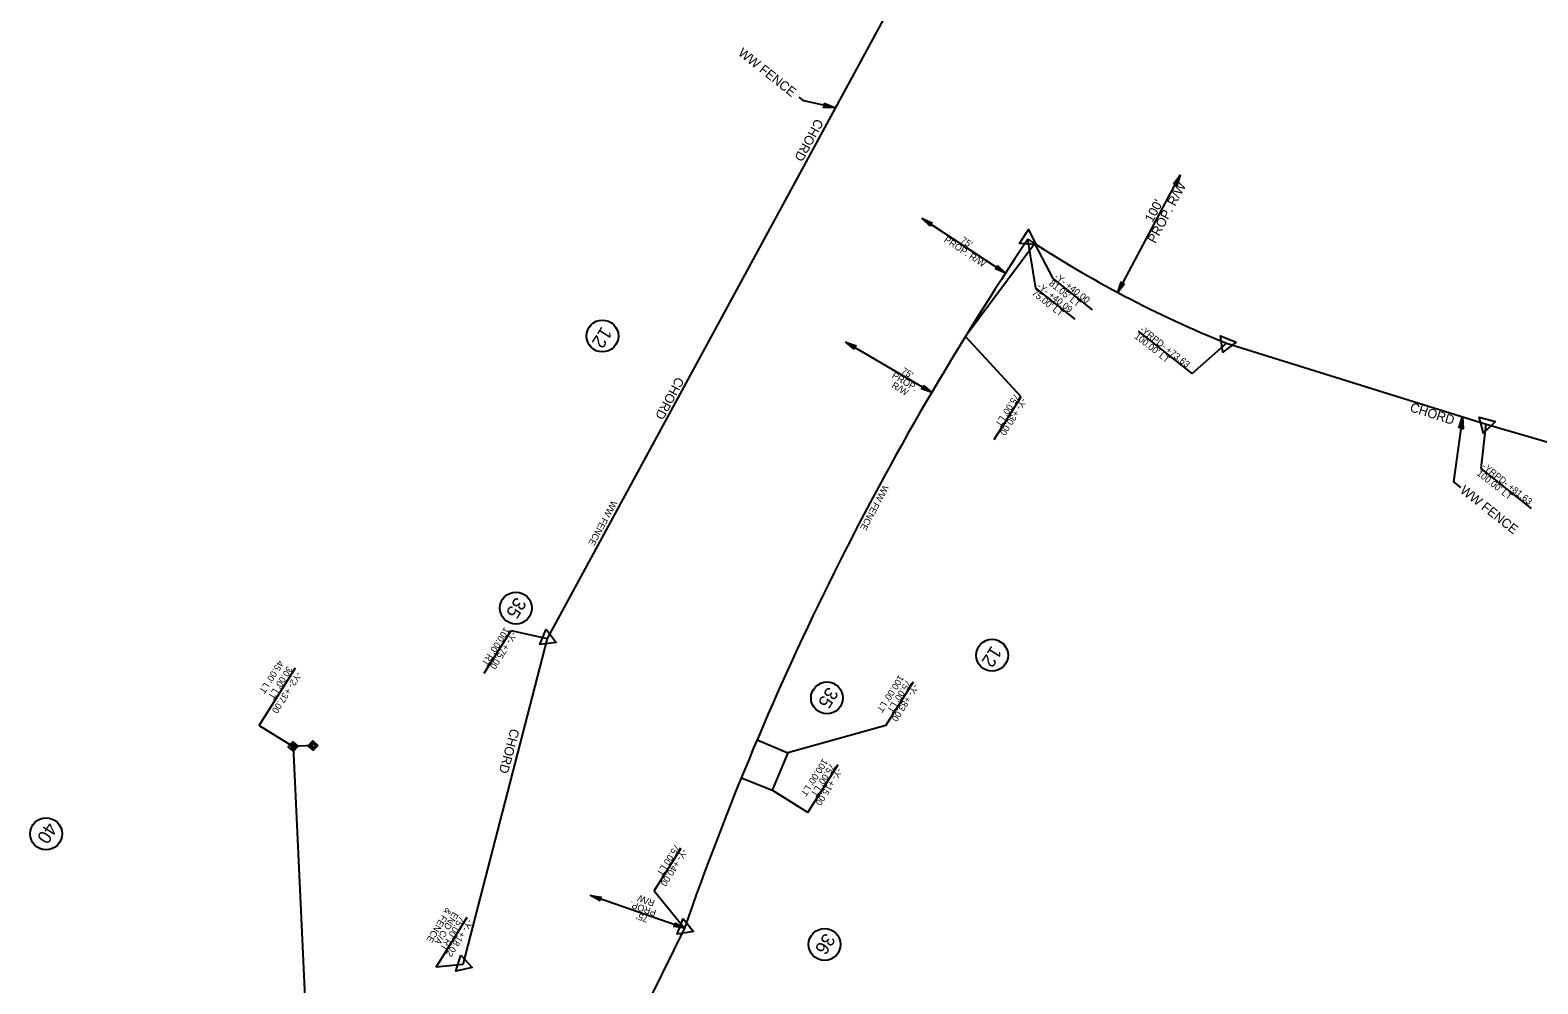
# Model space of a CAD drawing. Extents: x 1779796 to 1783527, y 810952 to 815815.
# Drawn here: x 1780686 to 1781820, y 812223 to 812940 of the extents above; entities that cross this region are included whole.
import ezdxf

# ---------------------------------------------------------------- set-up
doc = ezdxf.new("R2010")
doc.units = 0
for name, color, linetype in [('Prop Dimension', 7, 'Continuous'), ('Prop Dimension Text', 7, 'Continuous'), ('Prop Easement Construction', 7, 'Continuous'), ('Prop Easement Construction Station Offsets', 7, 'Continuous'), ('Prop Easement Permanent Utility', 7, 'Continuous'), ('Prop Easement Permanent Utility Station Offsets', 7, 'Continuous'), ('Prop Easement Temporary Drainage', 7, 'Continuous'), ('Prop Easement Temporary Drainage Station Offsets', 7, 'Continuous'), ('Prop Fence Woven Wire', 7, 'Continuous'), ('Prop Parcel Number CELL', 7, 'Continuous'), ('Prop Parcel Number Text', 7, 'Continuous'), ('Prop ROW Marker CELL', 7, 'Continuous'), ('Prop ROW Permanent Easement CELL', 7, 'Continuous'), ('Prop ROW RW CA Lines', 7, 'Continuous'), ('Prop ROW Station Offsets', 7, 'Continuous'), ('Prop Terminator CELL', 7, 'Continuous')]:
    doc.layers.add(name, color=color, linetype=linetype)

msp = doc.modelspace()

# ---------------------------------------------------------------- linework, layer by layer
at = {"layer": 'Prop Dimension'}
for p, q in [((1781267.9, 812886.9), (1781264.4, 812889.7)), ((1781291.6, 812881.6), (1781267.9, 812886.9)), ((1781504.1, 812742.7), (1781551.1, 812831)), ((1781356.9, 812798.3), (1781419.7, 812757.4)), ((1781299.4, 812705.5), (1781364.1, 812667.6)), ((1781763.4, 812649.3), (1781756.6, 812600.3)), ((1781756.6, 812600.3), (1781762, 812596.1)), ((1781178.2, 812264.6), (1781107.4, 812289.2))]:
    msp.add_line(p, q, dxfattribs=at)
at = {"layer": 'Prop Easement Construction'}
msp.add_line((1781441.6, 812779.5), (1781389.4, 812709.6), dxfattribs=at)
at = {"layer": 'Prop Easement Construction Station Offsets'}
for p, q in [((1781485.1, 812729.8), (1781455.5, 812753.3)), ((1781411.1, 812632.3), (1781431.3, 812664.2))]:
    msp.add_line(p, q, dxfattribs=at)
for points in [[(1781455.5, 812753.3), (1781441.6, 812779.5)], [(1781431.3, 812664.2), (1781389.4, 812709.6)]]:
    msp.add_lwpolyline(points, dxfattribs=at)
at = {"layer": 'Prop Easement Permanent Utility'}
for p, q in [((1780898.7, 812402), (1780883.7, 812401.3)), ((1780883.7, 812401.3), (1780902.3, 812002.2))]:
    msp.add_line(p, q, dxfattribs=at)
at = {"layer": 'Prop Easement Permanent Utility Station Offsets'}
for q in [(1780885.6, 812460.4), (1780883.7, 812401.3)]:
    msp.add_line((1780858.1, 812417), q, dxfattribs=at)
at = {"layer": 'Prop Easement Temporary Drainage'}
for p, q in [((1781232.8, 812406.4), (1781255.8, 812396.6)), ((1781255.8, 812396.6), (1781244, 812368.4)), ((1781220.9, 812377.8), (1781244, 812368.4))]:
    msp.add_line(p, q, dxfattribs=at)
at = {"layer": 'Prop Easement Temporary Drainage Station Offsets'}
for p, q in [((1781329.6, 812417.1), (1781350.4, 812449.9)), ((1781270.9, 812351.7), (1781293.7, 812387.7))]:
    msp.add_line(p, q, dxfattribs=at)
for points in [[(1781329.6, 812417.1), (1781255.8, 812396.6)], [(1781270.9, 812351.7), (1781244, 812368.4)]]:
    msp.add_lwpolyline(points, dxfattribs=at)
at = {"layer": 'Prop Fence Woven Wire'}
for p, q in [((1781332.6, 812957.1), (1781074.9, 812482.4)), ((1781585.9, 812704.6), (1781781.1, 812643.8)), ((1781781.1, 812643.8), (1781913.7, 812605.1)), ((1781074.9, 812482.4), (1781011.4, 812237.2)), ((1781178.2, 812264.6), (1781097.3, 812100.9))]:
    msp.add_line(p, q, dxfattribs=at)
for centre, radius, start, end in [((1783308.8, 811526), 2255, 146.1271, 160.8792), ((1781908.4, 813501.8), 860, 236.7199, 247.9703)]:
    msp.add_arc(centre, radius, start, end, dxfattribs=at)
at = {"layer": 'Prop Parcel Number CELL'}
for p, q in [((1781116.4, 812710), (1781116.4, 812710)), ((1781051.3, 812505.4), (1781051.3, 812505.4)), ((1781409.5, 812469.9), (1781409.5, 812469.9)), ((1781285.3, 812437.8), (1781285.3, 812437.8)), ((1780697.9, 812335.6), (1780697.9, 812335.6)), ((1781283.5, 812252.4), (1781283.5, 812252.4))]:
    msp.add_line(p, q, dxfattribs=at)
for centre in [(1781116.4, 812710), (1781051.3, 812505.4), (1781409.5, 812469.9), (1781285.3, 812437.8), (1780697.9, 812335.6), (1781283.5, 812252.4)]:
    msp.add_circle(centre, 12, dxfattribs=at)
at = {"layer": 'Prop ROW Marker CELL'}
for p, q in [((1781436.5, 812782.8), (1781436.5, 812782.8)), ((1781585.9, 812704.6), (1781585.9, 812704.6)), ((1781781.1, 812643.8), (1781781.1, 812643.8)), ((1781074.9, 812482.4), (1781074.9, 812482.4)), ((1780883.7, 812401.3), (1780883.7, 812401.3)), ((1780898.7, 812402), (1780898.7, 812402)), ((1781178.2, 812264.6), (1781178.2, 812264.6)), ((1781011.4, 812237.2), (1781011.4, 812237.2))]:
    msp.add_line(p, q, dxfattribs=at)
for points in [[(1781442.5, 812778.8), (1781430.1, 812779.6), (1781437, 812790)], [(1781593, 812705.5), (1781583.2, 812697.9), (1781581.4, 812710.2)], [(1781788.1, 812645.7), (1781779.3, 812636.9), (1781776, 812648.9)], [(1781074.1, 812489.6), (1781081.6, 812479.6), (1781069.2, 812478.1)], [(1781177.2, 812271.8), (1781184.9, 812262), (1781172.6, 812260.1)], [(1781009.8, 812244.3), (1781018.3, 812235.1), (1781006.1, 812232.3)]]:
    msp.add_lwpolyline(points, close=True, dxfattribs=at)
at = {"layer": 'Prop ROW Permanent Easement CELL'}
for points in [[(1780887.3, 812401.4), (1780883.9, 812397.7), (1780880.1, 812401.1), (1780883.5, 812404.9)], [(1780885.5, 812401.4), (1780883.8, 812399.5), (1780881.9, 812401.2), (1780883.6, 812403.1)], [(1780902.3, 812402.1), (1780898.8, 812398.4), (1780895.1, 812401.8), (1780898.5, 812405.6)], [(1780900.5, 812402.1), (1780898.8, 812400.2), (1780896.9, 812401.9), (1780898.6, 812403.8)]]:
    msp.add_lwpolyline(points, close=True, dxfattribs=at)
at = {"layer": 'Prop ROW RW CA Lines'}
for p, q in [((1781781.1, 812643.8), (1781913.7, 812605.1)), ((1781074.9, 812482.4), (1781011.4, 812237.2)), ((1781178.2, 812264.6), (1781097.3, 812100.9))]:
    msp.add_line(p, q, dxfattribs=at)
for points in [[(1781332.6, 812957.1), (1781074.9, 812482.4)], [(1781585.9, 812704.6), (1781781.1, 812643.8)]]:
    msp.add_lwpolyline(points, dxfattribs=at)
for centre, radius, start, end in [((1783308.8, 811526), 2255, 146.1271, 160.8792), ((1781908.4, 813501.8), 860, 236.7199, 247.9703)]:
    msp.add_arc(centre, radius, start, end, dxfattribs=at)
at = {"layer": 'Prop ROW Station Offsets'}
for p, q in [((1781472, 812722.6), (1781442.5, 812746)), ((1781559.9, 812681.7), (1781519.7, 812713.6)), ((1781815.2, 812580.4), (1781777.3, 812610.4)), ((1781027.4, 812456.5), (1781047.7, 812488.4)), ((1781155.3, 812292.8), (1781175.6, 812324.8)), ((1781155.3, 812292.8), (1781178.2, 812264.6)), ((1780991.3, 812235.4), (1781014.7, 812273)), ((1781011.4, 812237.2), (1780991.3, 812235.4))]:
    msp.add_line(p, q, dxfattribs=at)
for points in [[(1781442.5, 812746), (1781436.5, 812782.8)], [(1781559.9, 812681.7), (1781585.9, 812704.6)], [(1781777.3, 812610.4), (1781781.1, 812643.8)], [(1781047.7, 812488.4), (1781074.9, 812482.4)]]:
    msp.add_lwpolyline(points, dxfattribs=at)
at = {"layer": 'Prop Terminator CELL'}
for points in [[(1781283.1, 812885.1), (1781291.6, 812881.6), (1781282.4, 812882), (1781283.9, 812883.3)], [(1781546.1, 812824.5), (1781551.1, 812831), (1781548.6, 812823.1), (1781547.8, 812824.7)], [(1781362.9, 812792.7), (1781356.9, 812798.3), (1781364.5, 812795.1), (1781362.8, 812794.4)], [(1781413.7, 812763), (1781419.7, 812757.4), (1781412.1, 812760.6), (1781413.7, 812761.2)], [(1781509.1, 812749.2), (1781504.1, 812742.7), (1781506.7, 812750.6), (1781507.4, 812749)], [(1781305.7, 812700.2), (1781299.4, 812705.5), (1781307.2, 812702.6), (1781305.6, 812701.9)], [(1781357.8, 812672.9), (1781364.1, 812667.6), (1781356.4, 812670.4), (1781358, 812671.2)], [(1781760.7, 812640.6), (1781763.4, 812649.3), (1781763.8, 812640.1), (1781762.4, 812641.5)], [(1781114.6, 812285.2), (1781107.4, 812289.2), (1781115.5, 812287.9), (1781114.1, 812286.9)], [(1781171, 812268.6), (1781178.2, 812264.6), (1781170, 812265.9), (1781171.5, 812267)]]:
    msp.add_lwpolyline(points, close=True, dxfattribs=at)

# ---------------------------------------------------------------- texts
at = {"layer": 'Prop Dimension Text'}
for s, height, rotation, p in [('WW FENCE', 7, 321.6309, (1781217.9, 812921.8)), ('CHORD', 7, 241.5491, (1781276.9, 812874)), ('PROP. R/W', 7, 61.9551, (1781532.2, 812779.2)), ("100'", 7, 61.9551, (1781530.2, 812794.9)), ('PROP. R/W', 5, 326.335, (1781372.9, 812781.3)), ("75'", 5, 326.335, (1781385.4, 812780.9)), ("75'", 5, 329.0187, (1781340.7, 812682.4)), ('CHORD', 7, 241.5491, (1781172.1, 812679.8)), ('R/W', 5, 329.0187, (1781333.5, 812671.5)), ('PROP.', 5, 329.0187, (1781333.7, 812679)), ('CHORD', 7, 342.367, (1781723.3, 812653.5)), ('WW FENCE', 5, 242.0444, (1781327.5, 812598.3)), ('WW FENCE', 7, 321.6309, (1781761, 812592.8)), ('WW FENCE', 5, 241.541, (1781123.3, 812586.7)), ('CHORD', 7, 255.0712, (1781047.3, 812415.2)), ('R/W', 5, 160.1616, (1781156.2, 812285.5)), ('PROP.', 5, 160.1616, (1781157.4, 812278.1)), ("75'", 5, 160.1616, (1781151.3, 812273.4))]:
    msp.add_text(s, height=height, rotation=rotation, dxfattribs=at).set_placement(p)
at = {"layer": 'Prop Easement Construction Station Offsets'}
for s, rotation, p in [('-Y- +40.00', 321.6309, (1781456, 812753.8)), ("81.05' LT", 321.6309, (1781451.9, 812748.7)), ("75.00' LT", 237.6015, (1781426.4, 812667.2)), ('-Y- +30.00', 237.6015, (1781431.9, 812663.8))]:
    msp.add_text(s, height=5, rotation=rotation, dxfattribs=at).set_placement(p)
at = {"layer": 'Prop Easement Permanent Utility Station Offsets'}
for s, p in [("45.00' LT", (1780872.8, 812466.5)), ("30.00' LT", (1780879.5, 812462.2)), ('-Y2- +37.00', (1780886.3, 812457.9))]:
    msp.add_text(s, height=5, rotation=237.5792, dxfattribs=at).set_placement(p)
at = {"layer": 'Prop Easement Temporary Drainage Station Offsets'}
for s, p in [("100.00' LT", (1781339.5, 812455.5)), ("75.00' LT", (1781345, 812452)), ('-Y- +83.00', (1781350.5, 812448.6)), ("100.00' LT", (1781282.2, 812392.5)), ("75.00' LT", (1781287.7, 812389)), ('-Y- +15.00', (1781293.2, 812385.5))]:
    msp.add_text(s, height=5, rotation=237.6004, dxfattribs=at).set_placement(p)
at = {"layer": 'Prop Parcel Number Text'}
for s, p in [('12', (1781116, 812717.7)), ('35', (1781051.4, 812514.3)), ('12', (1781409.2, 812477.7)), ('35', (1781286.1, 812446.8)), ('40', (1780698.6, 812345)), ('36', (1781283.8, 812261.6))]:
    msp.add_text(s, height=10, rotation=237.6004, dxfattribs=at).set_placement(p)
at = {"layer": 'Prop ROW Station Offsets'}
for s, rotation, p in [("75.00' LT", 321.6309, (1781439, 812741.5)), ('-Y- +40.09', 321.6309, (1781443, 812746.6)), ("100.00' LT", 321.6309, (1781516.1, 812709)), ('-YRPD- +73.63', 321.6309, (1781520.2, 812714.1)), ("100.00' LT", 321.6309, (1781773.7, 812605.9)), ('-YRPD- +81.63', 321.6309, (1781777.7, 812611)), ("100.00' RT", 237.6004, (1781042.8, 812491.4)), ('-Y- +75.00', 237.6004, (1781048.3, 812488)), ('75.00 LT', 237.6015, (1781171.1, 812328.3)), ('-Y- +40.00', 237.6015, (1781176.6, 812324.8)), ('& FENCE', 238.0567, (1780999.1, 812280.4)), ('END C/A', 238.0567, (1781004.2, 812277.3)), ("75.00' RT", 238.0567, (1781009.3, 812274.1)), ('-Y- +18.02', 238.0567, (1781015.1, 812271.8))]:
    msp.add_text(s, height=5, rotation=rotation, dxfattribs=at).set_placement(p)

doc.saveas('drawing.dxf')
